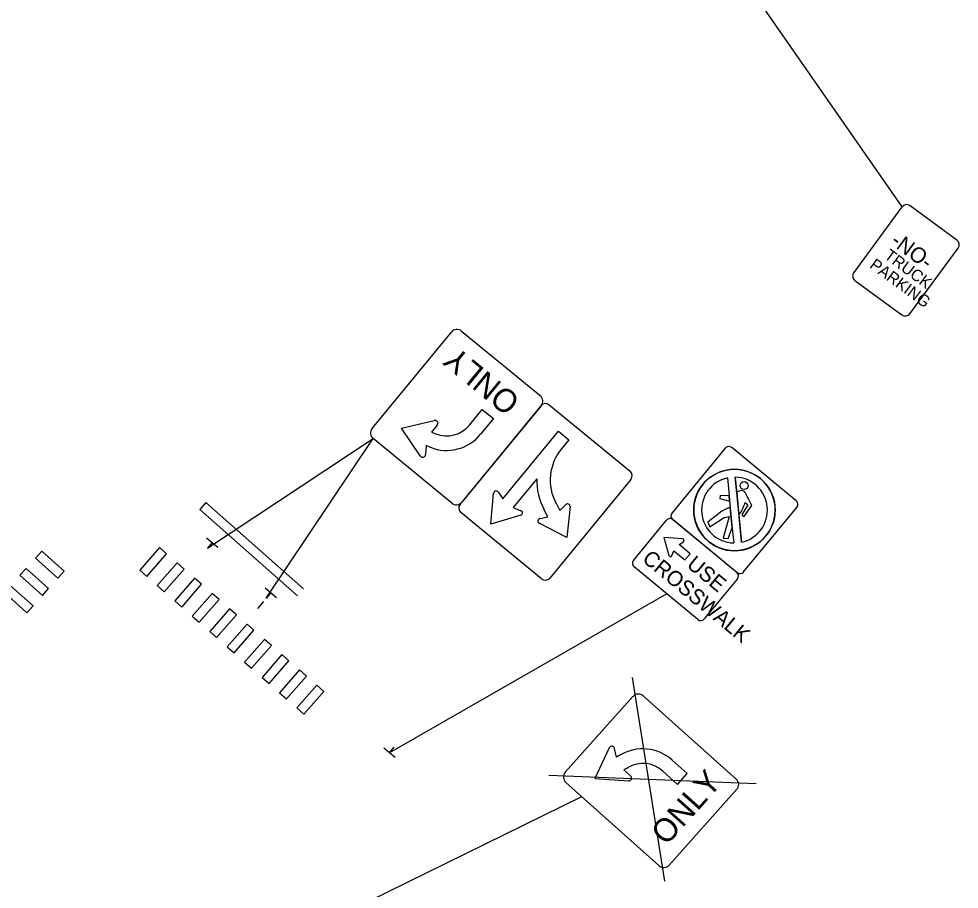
# Model space of a CAD drawing. Extents: x 1472333 to 1475205, y 385587 to 386650.
# Drawn here: x 1473144.2 to 1473346.7, y 385779.2 to 385966.6 of the extents above; entities that cross this region are included whole.
import ezdxf

# ---------------------------------------------------------------- set-up
doc = ezdxf.new("R2010")
doc.units = 0
for name, color, linetype in [('_CIVIL_CONSTRUCTION', 7, 'Continuous'), ('RS_Raster1', 7, 'Continuous'), ('RW_X_CL', 7, 'Continuous'), ('RW_X_CL_500_Cardinal_Points', 7, 'Continuous'), ('SC_Scratch1', 7, 'Continuous')]:
    doc.layers.add(name, color=color, linetype=linetype)

msp = doc.modelspace()

# ---------------------------------------------------------------- linework, layer by layer
at = {"layer": '_CIVIL_CONSTRUCTION'}
for p, q in [((1473298.51, 385867.9), (1473299.85, 385853.88)), ((1473295.28, 385863.97), (1473295.22, 385863.26)), ((1473295.28, 385863.97), (1473295.22, 385863.26)), ((1473295.22, 385863.26), (1473297.32, 385862.71)), ((1473295.22, 385863.26), (1473297.32, 385862.71)), ((1473297.2, 385863.88), (1473295.28, 385863.97)), ((1473297.2, 385863.88), (1473295.28, 385863.97)), ((1473297.32, 385862.71), (1473297.29, 385862.95)), ((1473298.83, 385864.6), (1473298.84, 385864.45)), ((1473298.84, 385864.45), (1473299.28, 385859.91)), ((1473296.91, 385861.2), (1473295.63, 385860.59)), ((1473296.91, 385861.2), (1473295.63, 385860.59)), ((1473297.44, 385861.42), (1473296.91, 385861.2)), ((1473297.44, 385861.42), (1473296.91, 385861.2)), ((1473297.45, 385861.34), (1473297.44, 385861.42)), ((1473297.87, 385856.99), (1473297.45, 385861.34)), ((1473301.23, 385861.96), (1473299.9, 385859.77)), ((1473301.23, 385861.96), (1473299.9, 385859.77)), ((1473300.35, 385859.32), (1473302.08, 385861.77)), ((1473300.35, 385859.32), (1473302.08, 385861.77)), ((1473300.68, 385862.45), (1473301.23, 385861.96)), ((1473300.68, 385862.45), (1473301.23, 385861.96)), ((1473302.08, 385861.77), (1473302.07, 385861.78)), ((1473302.08, 385861.77), (1473302.07, 385861.78)), ((1473295.63, 385860.59), (1473292.58, 385858.2)), ((1473295.63, 385860.59), (1473292.58, 385858.2)), ((1473293.05, 385857.16), (1473296.1, 385859.21)), ((1473293.05, 385857.16), (1473296.1, 385859.21)), ((1473297.23, 385859.45), (1473295.88, 385854.72)), ((1473297.23, 385859.45), (1473295.88, 385854.72)), ((1473296.1, 385859.21), (1473297.23, 385859.45)), ((1473296.1, 385859.21), (1473297.23, 385859.45)), ((1473299.9, 385859.77), (1473300.35, 385859.32)), ((1473299.9, 385859.77), (1473300.35, 385859.32)), ((1473292.58, 385858.2), (1473293.05, 385857.16)), ((1473292.58, 385858.2), (1473293.05, 385857.16)), ((1473296.99, 385854.67), (1473297.87, 385856.99)), ((1473296.99, 385854.67), (1473297.87, 385856.99)), ((1473184.65, 385854.85), (1473187.11, 385852.8)), ((1473287.18, 385854.62), (1473283.14, 385854.93)), ((1473283.14, 385854.93), (1473284.21, 385851.02)), ((1473295.88, 385854.72), (1473296.99, 385854.67)), ((1473295.88, 385854.72), (1473296.99, 385854.67)), ((1473185.88, 385853.83), (1473184.86, 385852.6)), ((1473285.76, 385852.77), (1473285.76, 385852.77)), ((1473286.4, 385853.38), (1473287.34, 385853.99)), ((1473286.41, 385853.37), (1473286.4, 385853.38)), ((1473288.78, 385851.41), (1473286.41, 385853.37)), ((1473284.86, 385850.99), (1473285.28, 385852.03)), ((1473287.66, 385850.06), (1473288.78, 385851.41)), ((1473197.28, 385844.05), (1473199.74, 385841.99)), ((1473198.51, 385843.02), (1473197.49, 385841.79)), ((1473283.75, 385842.77), (1473224.06, 385808.52)), ((1473225.3, 385807.51), (1473222.82, 385809.53)), ((1473224.06, 385808.52), (1473225.07, 385809.76))]:
    msp.add_line(p, q, dxfattribs=at)
for points in [[(1473296.35, 385874.1), (1473284.9, 385860.22)], [(1473311.64, 385862.78), (1473297.76, 385874.24)], [(1473296.83, 385867.73), (1473297.2, 385863.92), (1473297.3, 385862.95), (1473297.29, 385862.95)], [(1473298.84, 385864.45), (1473298.51, 385867.9)], [(1473297.29, 385862.95), (1473297.2, 385863.88), (1473297.2, 385863.88)], [(1473297.29, 385862.95), (1473297.45, 385861.34), (1473297.95, 385856.12), (1473298.19, 385853.72)], [(1473299.85, 385853.88), (1473299.32, 385859.44), (1473299.32, 385859.44), (1473299.32, 385859.44), (1473298.84, 385864.45), (1473298.84, 385864.45)], [(1473298.84, 385864.45), (1473298.84, 385864.45)], [(1473300.32, 385847.49), (1473311.78, 385861.37)], [(1473285.03, 385858.81), (1473298.91, 385847.35)], [(1473285.11, 385858.75), (1473298.84, 385847.41)], [(1473276.58, 385849.97), (1473283.71, 385858.62)], [(1473285.29, 385852.02), (1473287.66, 385850.06)], [(1473290.44, 385837.24), (1473276.71, 385848.58)], [(1473298.97, 385846.02), (1473291.84, 385837.37)]]:
    msp.add_lwpolyline(points, dxfattribs=at)
for centre, radius in [((1473298.34, 385860.81), 8.77), ((1473300.4, 385866.08), 0.864)]:
    msp.add_circle(centre, radius, dxfattribs=at)
for centre, radius, start, end in [((1473297.12, 385873.47), 1, 50.4683, 140.4683), ((1473298.34, 385860.81), 8.77, 320.4683, 140.4683), ((1473298.34, 385860.81), 7.09, 102.3162, 268.7162), ((1473298.34, 385860.81), 7.09, 102.3162, 268.7162), ((1473298.34, 385860.81), 7.09, 282.2874, 88.6396), ((1473298.34, 385860.81), 7.09, 282.2874, 88.6396), ((1473298.34, 385860.81), 8.77, 140.4683, 320.4683), ((1473299.18, 385862.95), 1.54, 102.5435, 102.5966), ((1473311.01, 385862.01), 1, 320.4683, 50.4683), ((1473284.48, 385857.99), 0.989, 50.4683, 140.4683), ((1473285.67, 385859.58), 1, 140.4683, 230.4683), ((1473287.15, 385854.28), 0.342, 302.8305, 85.5475), ((1473284.54, 385851.11), 0.342, 195.389, 338.1061), ((1473277.34, 385849.34), 0.989, 140.4683, 230.4683), ((1473298.21, 385846.65), 0.989, 320.4683, 50.4683), ((1473299.55, 385848.13), 1, 230.4683, 320.4683), ((1473291.07, 385838), 0.989, 230.4683, 320.4683)]:
    msp.add_arc(centre, radius, start, end, dxfattribs=at)
for points in [[(1473302.07, 385861.78), (1473301.63, 385862.65), (1473300.97, 385864.02), (1473300.72, 385864.52), (1473300.61, 385864.65), (1473300.48, 385864.76), (1473300.17, 385865.02), (1473299.48, 385864.97), (1473299.08, 385864.74), (1473298.83, 385864.6)], [(1473302.07, 385861.78), (1473301.63, 385862.65), (1473300.97, 385864.02), (1473300.72, 385864.52), (1473300.61, 385864.65), (1473300.48, 385864.76), (1473300.17, 385865.02), (1473299.48, 385864.97), (1473299.08, 385864.74), (1473298.83, 385864.6)], [(1473299.28, 385859.91), (1473299.35, 385859.95), (1473299.53, 385860.06), (1473299.79, 385860.44), (1473299.99, 385860.81), (1473300.3, 385861.5), (1473300.5, 385861.98), (1473300.68, 385862.45)], [(1473299.28, 385859.91), (1473299.35, 385859.95), (1473299.53, 385860.06), (1473299.79, 385860.44), (1473299.99, 385860.81), (1473300.3, 385861.5), (1473300.5, 385861.98), (1473300.68, 385862.45)]]:
    msp.add_open_spline(points, degree=3, dxfattribs=at)
at = {"layer": 'RS_Raster1'}
for p, q in [((1473184.52, 385862.42), (1473183.2, 385860.91)), ((1473183.2, 385860.91), (1473204.25, 385842.36)), ((1473205.57, 385843.87), (1473184.52, 385862.42)), ((1473196.92, 385841.13), (1473195.62, 385839.61))]:
    msp.add_line(p, q, dxfattribs=at)
at = {"layer": 'RW_X_CL'}
msp.add_line((1473302.04, 385972.65), (1473334.41, 385926.07), dxfattribs=at)
for points in [[(1473334.41, 385926.07), (1473324.02, 385911.99)], [(1473346.22, 385918.92), (1473336.16, 385926.34)], [(1473336.1, 385903.09), (1473346.48, 385917.17)], [(1473324.29, 385910.24), (1473334.35, 385902.82)]]:
    msp.add_lwpolyline(points, dxfattribs=at)
for centre, start, end in [((1473335.42, 385925.33), 53.5862, 143.5862), ((1473345.48, 385917.91), 323.5862, 53.5862), ((1473325.03, 385911.25), 143.5862, 233.5862), ((1473335.09, 385903.83), 233.5862, 323.5862)]:
    msp.add_arc(centre, 1.25, start, end, dxfattribs=at)
at = {"layer": 'RW_X_CL_500_Cardinal_Points'}
for p, q in [((1473241.27, 385879.1), (1473244.05, 385882.48)), ((1473244.05, 385882.48), (1473246.46, 385880.5)), ((1473226.61, 385878.47), (1473233.7, 385880.09)), ((1473234.32, 385879.09), (1473233.11, 385877.59)), ((1473246.46, 385880.5), (1473243.69, 385877.12)), ((1473230.68, 385872.45), (1473226.61, 385878.47)), ((1473233.11, 385877.59), (1473234.03, 385877.22)), ((1473248.46, 385863.23), (1473260.42, 385877.8)), ((1473260.42, 385877.8), (1473262.68, 385875.95)), ((1473184.87, 385852.61), (1473220.54, 385876.18)), ((1473197.5, 385841.81), (1473220.54, 385876.18)), ((1473262.68, 385875.95), (1473261.09, 385874.01)), ((1473231.96, 385874.68), (1473231.82, 385872.75)), ((1473232.88, 385874.31), (1473231.96, 385874.68)), ((1473255.76, 385867.53), (1473250.71, 385861.38)), ((1473245.88, 385857.79), (1473246.49, 385864.46)), ((1473247.44, 385864.71), (1473248.46, 385863.23)), ((1473250.71, 385861.38), (1473252.37, 385860.66)), ((1473258.19, 385859.34), (1473257.36, 385860.88)), ((1473259.93, 385862.26), (1473260.76, 385860.72)), ((1473260.76, 385860.72), (1473262.05, 385861.97)), ((1473262.93, 385861.54), (1473262.23, 385854.88)), ((1473252.31, 385859.69), (1473245.88, 385857.79)), ((1473256.43, 385858.96), (1473258.19, 385859.34)), ((1473262.23, 385854.88), (1473256.29, 385857.99)), ((1473283.35, 385780.93), (1473276.36, 385824.74)), ((1473271.36, 385809.6), (1473268.26, 385803.02)), ((1473272.97, 385807.59), (1473272.53, 385809.48)), ((1473273.82, 385808.1), (1473272.97, 385807.59)), ((1473288.19, 385804.07), (1473284.93, 385806.98)), ((1473274.55, 385804.9), (1473275.4, 385805.4)), ((1473275.98, 385803.6), (1473274.55, 385804.9)), ((1473282.85, 385804.65), (1473286.11, 385801.74)), ((1473286.11, 385801.74), (1473288.19, 385804.07)), ((1473258.38, 385803.75), (1473303, 385801.92)), ((1473268.26, 385803.02), (1473275.51, 385802.51)), ((1473191.19, 385762.67), (1473265.45, 385799.11))]:
    msp.add_line(p, q, dxfattribs=at)
for points in [[(1473239.58, 385899.36), (1473256.49, 385885.48)], [(1473220.32, 385878.38), (1473237.38, 385899.14)], [(1473239.25, 385862.03), (1473256.7, 385883.28)], [(1473256.7, 385883.28), (1473239.65, 385862.51)], [(1473258.46, 385883.45), (1473275.85, 385869.17)], [(1473237.45, 385862.29), (1473220.54, 385876.18)], [(1473276.02, 385867.41), (1473258.57, 385846.16)], [(1473256.81, 385845.99), (1473239.42, 385860.27)], [(1473276.49, 385820.67), (1473261.91, 385804.37)], [(1473298.73, 385802.88), (1473278.7, 385820.8)], [(1473262.04, 385802.16), (1473282.07, 385784.25)], [(1473284.28, 385784.37), (1473298.86, 385800.68)]]:
    msp.add_lwpolyline(points, dxfattribs=at)
for centre, radius, start, end in [((1473238.59, 385898.15), 1.56, 50.6074, 140.6074), ((1473255.49, 385884.27), 1.56, 320.6074, 50.6074), ((1473257.67, 385882.49), 1.25, 50.6074, 140.6074), ((1473233.84, 385879.48), 0.625, 321.0814, 102.8531), ((1473236.36, 385883.13), 6.35, 248.4687, 320.6074), ((1473221.53, 385877.38), 1.56, 140.6074, 230.6074), ((1473236.36, 385883.13), 9.48, 248.4649, 320.6074), ((1473269.3, 385867.27), 10.63, 140.6074, 208.1687), ((1473231.2, 385872.8), 0.625, 214.0421, 355.8138), ((1473275.06, 385868.21), 1.25, 320.6074, 50.6074), ((1473269.3, 385867.27), 13.54, 178.9223, 208.1687), ((1473247.01, 385864.42), 0.521, 34.5631, 174.7984), ((1473238.44, 385863.5), 1.56, 230.6074, 320.6074), ((1473240.21, 385861.23), 1.25, 140.6074, 230.6074), ((1473262.41, 385861.6), 0.521, 353.9777, 134.213), ((1473252.16, 385860.19), 0.521, 286.4164, 66.6517), ((1473256.53, 385858.45), 0.521, 102.1244, 242.3597), ((1473257.6, 385846.95), 1.25, 230.6074, 320.6074), ((1473277.66, 385819.63), 1.56, 48.2, 138.2), ((1473271.93, 385809.34), 0.625, 12.9936, 154.7653), ((1473278.61, 385799.91), 9.48, 48.2, 120.3425), ((1473278.61, 385799.91), 6.35, 48.2, 120.3387), ((1473263.08, 385803.33), 1.56, 138.2, 228.2), ((1473275.56, 385803.13), 0.625, 265.9543, 47.726), ((1473297.69, 385801.72), 1.56, 318.2, 48.2), ((1473283.11, 385785.41), 1.56, 228.2, 318.2)]:
    msp.add_arc(centre, radius, start, end, dxfattribs=at)
at = {"layer": 'SC_Scratch1'}
for points in [[(1473174.57, 385852.73), (1473170.29, 385847.83), (1473171.79, 385846.52), (1473176.08, 385851.41)], [(1473147.84, 385850.48), (1473152.68, 385846.13), (1473154.01, 385847.62), (1473149.18, 385851.96)], [(1473178.33, 385849.43), (1473174.05, 385844.54), (1473175.56, 385843.22), (1473179.84, 385848.11)], [(1473144.5, 385846.76), (1473149.33, 385842.41), (1473150.67, 385843.9), (1473145.84, 385848.24)], [(1473141.16, 385843.04), (1473145.99, 385838.69), (1473147.33, 385840.18), (1473142.49, 385844.52)], [(1473182.1, 385846.14), (1473177.81, 385841.25), (1473179.32, 385839.93), (1473183.6, 385844.82)], [(1473185.86, 385842.84), (1473181.57, 385837.95), (1473183.08, 385836.64), (1473187.36, 385841.53)], [(1473189.62, 385839.55), (1473185.34, 385834.66), (1473186.84, 385833.34), (1473191.12, 385838.23)], [(1473193.38, 385836.26), (1473189.1, 385831.37), (1473190.6, 385830.05), (1473194.88, 385834.94)], [(1473197.14, 385832.96), (1473192.86, 385828.07), (1473194.36, 385826.75), (1473198.65, 385831.64)], [(1473200.9, 385829.67), (1473196.62, 385824.78), (1473198.13, 385823.46), (1473202.41, 385828.35)], [(1473204.66, 385826.37), (1473200.38, 385821.48), (1473201.89, 385820.17), (1473206.17, 385825.06)], [(1473208.43, 385823.08), (1473204.14, 385818.19), (1473205.65, 385816.87), (1473209.93, 385821.76)]]:
    msp.add_lwpolyline(points, close=True, dxfattribs=at)

# ---------------------------------------------------------------- texts
at = {"layer": '_CIVIL_CONSTRUCTION'}
for s, p in [('CROSSWALK', (1473278.27, 385849.94)), ('USE', (1473287.85, 385848.7))]:
    msp.add_text(s, height=3.296, rotation=320.4683, dxfattribs=at).set_placement(p)
at = {"layer": 'RW_X_CL'}
for s, height, p in [('-NO-', 3.333, (1473331.76, 385918.19)), ('TRUCK', 2.5, (1473330.39, 385915.16)), ('PARKING', 2.5, (1473327.26, 385913.14))]:
    msp.add_text(s, height=height, rotation=323.5862, dxfattribs=at).set_placement(p)
at = {"layer": 'RW_X_CL_500_Cardinal_Points'}
for rotation, p in [(140.6074, (1473252.5, 385884.71)), (48.2, (1473283.68, 385788.39))]:
    msp.add_text('ONLY', height=5, rotation=rotation, dxfattribs=at).set_placement(p)

doc.saveas('drawing.dxf')
